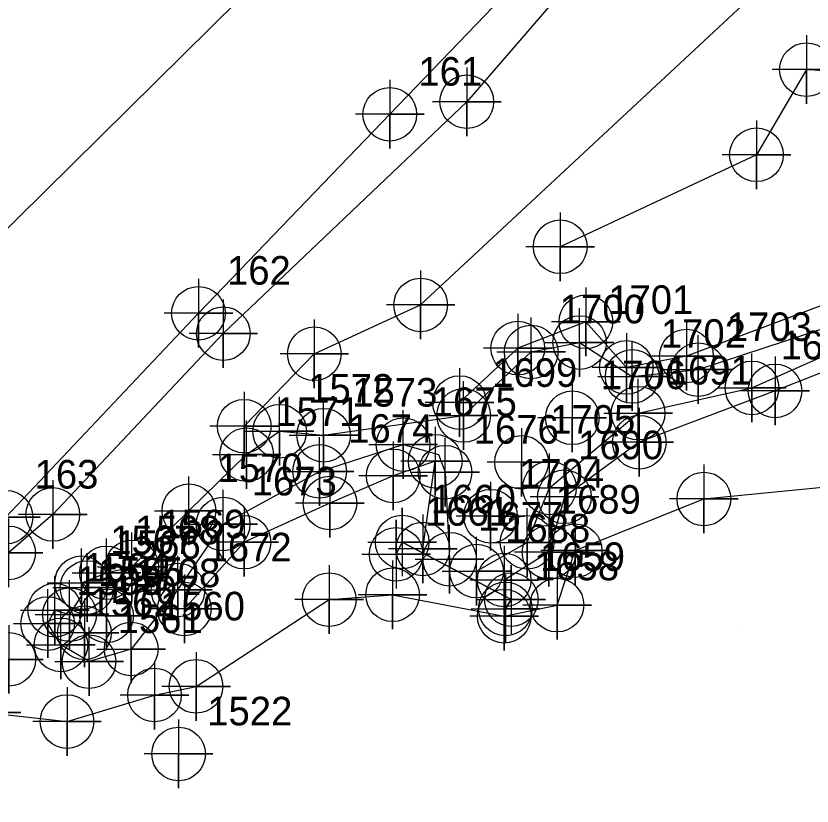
# Model space of a CAD drawing. Extents: x 1497074 to 1501343, y 481943 to 486114.
# Drawn here: x 1498485.9 to 1498555.5, y 484666.2 to 484735.3 of the extents above; entities that cross this region are included whole.
import ezdxf

# ---------------------------------------------------------------- set-up
doc = ezdxf.new("R2010")
doc.units = 0
for name, color, linetype in [('Exist DTM Breakline', 7, 'Continuous'), ('Exist DTM Breakline Cogo Point CELL', 7, 'Continuous'), ('Exist DTM Crownline', 7, 'Continuous'), ('Exist DTM Regular Point CELL', 7, 'Continuous'), ('Exist DTM Regular Point Cogo Number', 7, 'Continuous'), ('Exist DTM Regular Point Underwater CELL', 7, 'Continuous'), ('Exist DTM Regular Point Underwater Cogo Number', 7, 'Continuous'), ('Exist Hydro Stream or Body of Water', 7, 'Continuous'), ('Exist Hydro Stream or Body of Water Cogo Number', 7, 'Continuous'), ('Exist Hydro Stream or Body of Water Cogo Point CELL', 7, 'Continuous'), ('Exist Roads EOP', 7, 'Continuous'), ('Exist Roads EOP Cogo Number', 7, 'Continuous'), ('Exist Roads EOP Cogo Point CELL', 7, 'Continuous'), ('Exist Structure Minor Head and End Wall', 7, 'Continuous'), ('Exist Structure Minor Head and End Wall Cogo Number', 7, 'Continuous'), ('Exist Structure Minor Head and End Wall Cogo Point CELL', 7, 'Continuous'), ('PH Exist DTM Point', 7, 'Continuous')]:
    doc.layers.add(name, color=color, linetype=linetype)

msp = doc.modelspace()

# ---------------------------------------------------------------- linework, layer by layer
at = {"layer": 'Exist DTM Breakline'}
for points in [[(1498543.578, 484748.875), (1498525.356, 484727.773), (1498504.076, 484707.501), (1498489.168, 484691.702), (1498485.309, 484688.338), (1498482.582, 484685.278), (1498481.928, 484681.956), (1498482.729, 484679.638), (1498478.749, 484676.924), (1498480.53, 484675.332), (1498483.374, 484674.389), (1498490.413, 484673.601), (1498498.06, 484675.918), (1498501.691, 484676.673)], [(1498505.902, 484699.415), (1498512.029, 484705.743), (1498521.323, 484710.01), (1498551.972, 484738.6)], [(1498587.71, 484722.019), (1498578.881, 484728.622), (1498555.037, 484730.577), (1498550.672, 484723.134), (1498533.525, 484715.099)], [(1498561.972, 484712.059), (1498544.554, 484705.545), (1498539.303, 484704.549), (1498535.765, 484708.54), (1498529.808, 484706.236), (1498524.726, 484701.476)], [(1498568.235, 484707.531), (1498564.12, 484707.137), (1498552.295, 484702.499), (1498540.434, 484698.014), (1498533.886, 484693.244), (1498532.536, 484688.396), (1498528.621, 484685.97)], [(1498521.507, 484688.681), (1498522.593, 484696.353), (1498518.929, 484695.07), (1498513.394, 484692.699), (1498505.886, 484689.276), (1498500.67, 484683.439)], [(1498533.242, 484683.778), (1498534.825, 484688.535), (1498546.08, 484693.052), (1498568.33, 484695.244)], [(1498519.188, 484688.217), (1498519.707, 484689.291), (1498529.247, 484684.262), (1498528.727, 484683.445)], [(1498501.691, 484676.673), (1498513.329, 484684.253), (1498518.872, 484684.681), (1498528.629, 484682.804), (1498533.242, 484683.778)]]:
    msp.add_lwpolyline(points, dxfattribs=at)
at = {"layer": 'Exist DTM Breakline Cogo Point CELL'}
for points in [[(1498555.037, 484733.577), (1498555.037, 484727.577), (1498555.037, 484730.577), (1498558.037, 484730.577), (1498552.037, 484730.577)], [(1498525.356, 484730.773), (1498525.356, 484724.773), (1498525.356, 484727.773), (1498528.356, 484727.773), (1498522.356, 484727.773)], [(1498550.672, 484726.134), (1498550.672, 484720.134), (1498550.672, 484723.134), (1498553.672, 484723.134), (1498547.672, 484723.134)], [(1498533.525, 484718.099), (1498533.525, 484712.099), (1498533.525, 484715.099), (1498536.525, 484715.099), (1498530.525, 484715.099)], [(1498521.323, 484713.01), (1498521.323, 484707.01), (1498521.323, 484710.01), (1498524.323, 484710.01), (1498518.323, 484710.01)], [(1498535.765, 484711.54), (1498535.765, 484705.54), (1498535.765, 484708.54), (1498538.765, 484708.54), (1498532.765, 484708.54)], [(1498504.076, 484710.501), (1498504.076, 484704.501), (1498504.076, 484707.501), (1498507.076, 484707.501), (1498501.076, 484707.501)], [(1498512.029, 484708.743), (1498512.029, 484702.743), (1498512.029, 484705.743), (1498515.029, 484705.743), (1498509.029, 484705.743)], [(1498529.808, 484709.236), (1498529.808, 484703.236), (1498529.808, 484706.236), (1498532.808, 484706.236), (1498526.808, 484706.236)], [(1498544.554, 484708.545), (1498544.554, 484702.545), (1498544.554, 484705.545), (1498547.554, 484705.545), (1498541.554, 484705.545)], [(1498539.303, 484707.549), (1498539.303, 484701.549), (1498539.303, 484704.549), (1498542.303, 484704.549), (1498536.303, 484704.549)], [(1498552.295, 484705.499), (1498552.295, 484699.499), (1498552.295, 484702.499), (1498555.295, 484702.499), (1498549.295, 484702.499)], [(1498524.726, 484704.476), (1498524.726, 484698.476), (1498524.726, 484701.476), (1498527.726, 484701.476), (1498521.726, 484701.476)], [(1498505.902, 484702.415), (1498505.902, 484696.415), (1498505.902, 484699.415), (1498508.902, 484699.415), (1498502.902, 484699.415)], [(1498540.434, 484701.014), (1498540.434, 484695.014), (1498540.434, 484698.014), (1498543.434, 484698.014), (1498537.434, 484698.014)], [(1498522.593, 484699.353), (1498522.593, 484693.353), (1498522.593, 484696.353), (1498525.593, 484696.353), (1498519.593, 484696.353)], [(1498518.929, 484698.07), (1498518.929, 484692.07), (1498518.929, 484695.07), (1498521.929, 484695.07), (1498515.929, 484695.07)], [(1498533.886, 484696.244), (1498533.886, 484690.244), (1498533.886, 484693.244), (1498536.886, 484693.244), (1498530.886, 484693.244)], [(1498513.394, 484695.699), (1498513.394, 484689.699), (1498513.394, 484692.699), (1498516.394, 484692.699), (1498510.394, 484692.699)], [(1498546.08, 484696.052), (1498546.08, 484690.052), (1498546.08, 484693.052), (1498549.08, 484693.052), (1498543.08, 484693.052)], [(1498489.168, 484694.702), (1498489.168, 484688.702), (1498489.168, 484691.702), (1498492.168, 484691.702), (1498486.168, 484691.702)], [(1498505.886, 484692.276), (1498505.886, 484686.276), (1498505.886, 484689.276), (1498508.886, 484689.276), (1498502.886, 484689.276)], [(1498485.309, 484691.338), (1498485.309, 484685.338), (1498485.309, 484688.338), (1498488.309, 484688.338), (1498482.309, 484688.338)], [(1498521.507, 484691.681), (1498521.507, 484685.681), (1498521.507, 484688.681), (1498524.507, 484688.681), (1498518.507, 484688.681)], [(1498532.536, 484691.396), (1498532.536, 484685.396), (1498532.536, 484688.396), (1498535.536, 484688.396), (1498529.536, 484688.396)], [(1498534.825, 484691.535), (1498534.825, 484685.535), (1498534.825, 484688.535), (1498537.825, 484688.535), (1498531.825, 484688.535)], [(1498528.621, 484688.97), (1498528.621, 484682.97), (1498528.621, 484685.97), (1498531.621, 484685.97), (1498525.621, 484685.97)], [(1498513.329, 484687.253), (1498513.329, 484681.253), (1498513.329, 484684.253), (1498516.329, 484684.253), (1498510.329, 484684.253)], [(1498518.872, 484687.681), (1498518.872, 484681.681), (1498518.872, 484684.681), (1498521.872, 484684.681), (1498515.872, 484684.681)], [(1498500.67, 484686.439), (1498500.67, 484680.439), (1498500.67, 484683.439), (1498503.67, 484683.439), (1498497.67, 484683.439)], [(1498533.242, 484686.778), (1498533.242, 484680.778), (1498533.242, 484683.778), (1498536.242, 484683.778), (1498530.242, 484683.778)], [(1498528.629, 484685.804), (1498528.629, 484679.804), (1498528.629, 484682.804), (1498531.629, 484682.804), (1498525.629, 484682.804)], [(1498485.324, 484682.036), (1498485.324, 484676.036), (1498485.324, 484679.036), (1498488.324, 484679.036), (1498482.324, 484679.036)], [(1498501.691, 484679.673), (1498501.691, 484673.673), (1498501.691, 484676.673), (1498504.691, 484676.673), (1498498.691, 484676.673)], [(1498498.06, 484678.918), (1498498.06, 484672.918), (1498498.06, 484675.918), (1498501.06, 484675.918), (1498495.06, 484675.918)], [(1498483.374, 484677.389), (1498483.374, 484671.389), (1498483.374, 484674.389), (1498486.374, 484674.389), (1498480.374, 484674.389)], [(1498490.413, 484676.601), (1498490.413, 484670.601), (1498490.413, 484673.601), (1498493.413, 484673.601), (1498487.413, 484673.601)]]:
    msp.add_lwpolyline(points, dxfattribs=at)
for centre in [(1498555.037, 484730.577), (1498525.356, 484727.773), (1498550.672, 484723.134), (1498533.525, 484715.099), (1498521.323, 484710.01), (1498535.765, 484708.54), (1498504.076, 484707.501), (1498512.029, 484705.743), (1498529.808, 484706.236), (1498544.554, 484705.545), (1498539.303, 484704.549), (1498552.295, 484702.499), (1498524.726, 484701.476), (1498505.902, 484699.415), (1498540.434, 484698.014), (1498522.593, 484696.353), (1498518.929, 484695.07), (1498533.886, 484693.244), (1498513.394, 484692.699), (1498546.08, 484693.052), (1498489.168, 484691.702), (1498505.886, 484689.276), (1498485.309, 484688.338), (1498521.507, 484688.681), (1498532.536, 484688.396), (1498534.825, 484688.535), (1498528.621, 484685.97), (1498513.329, 484684.253), (1498518.872, 484684.681), (1498500.67, 484683.439), (1498533.242, 484683.778), (1498528.629, 484682.804), (1498485.324, 484679.036), (1498501.691, 484676.673), (1498498.06, 484675.918), (1498490.413, 484673.601)]:
    msp.add_circle(centre, 2.344, dxfattribs=at)
at = {"layer": 'Exist DTM Crownline'}
msp.add_lwpolyline([(1498174.514, 484418.762), (1498211.757, 484454.633), (1498248.883, 484490.298), (1498287.28, 484525.885), (1498324.11, 484560.628), (1498360.291, 484595.61), (1498397.16, 484630.832), (1498419.582, 484652.786), (1498435.06, 484667.859), (1498471.558, 484703.237), (1498507.821, 484739.068), (1498544.952, 484775.099), (1498579.438, 484811.194), (1498593.315, 484825.813), (1498614.797, 484848.72), (1498648.903, 484888.105), (1498682.161, 484928.338), (1498714.314, 484969.374), (1498734.432, 484994.616)], dxfattribs=at)
at = {"layer": 'Exist DTM Regular Point CELL'}
msp.add_lwpolyline([(1498500.168, 484673.764), (1498500.168, 484667.764), (1498500.168, 484670.764), (1498503.168, 484670.764), (1498497.168, 484670.764)], dxfattribs=at)
msp.add_circle((1498500.168, 484670.764), 2.344, dxfattribs=at)
at = {"layer": 'Exist DTM Regular Point Underwater CELL'}
for points in [[(1498534.576, 484703.149), (1498534.576, 484697.149), (1498534.576, 484700.149), (1498537.576, 484700.149), (1498531.576, 484700.149)], [(1498530.142, 484699.255), (1498530.142, 484693.255), (1498530.142, 484696.255), (1498533.142, 484696.255), (1498527.142, 484696.255)], [(1498527.428, 484694.545), (1498527.428, 484688.545), (1498527.428, 484691.545), (1498530.428, 484691.545), (1498524.428, 484691.545)], [(1498493.874, 484685.839), (1498493.874, 484679.839), (1498493.874, 484682.839), (1498496.874, 484682.839), (1498490.874, 484682.839)], [(1498491.934, 484684.356), (1498491.934, 484678.356), (1498491.934, 484681.356), (1498494.934, 484681.356), (1498488.934, 484681.356)]]:
    msp.add_lwpolyline(points, dxfattribs=at)
for centre in [(1498534.576, 484700.149), (1498530.142, 484696.255), (1498527.428, 484691.545), (1498493.874, 484682.839), (1498491.934, 484681.356)]:
    msp.add_circle(centre, 2.344, dxfattribs=at)
at = {"layer": 'Exist Hydro Stream or Body of Water'}
for points in [[(1498525.079, 484700.351), (1498530.984, 484705.901), (1498535.215, 484706.724), (1498539.814, 484703.763), (1498545.581, 484704.355), (1498562.802, 484710.019)], [(1498526.209, 484686.747), (1498530.628, 484689.26), (1498532.582, 484694.022), (1498540.326, 484700.553), (1498550.282, 484702.757), (1498562.565, 484708.225), (1498565.15, 484709.125)], [(1498500.114, 484685.097), (1498496.028, 484679.939), (1498492.337, 484678.836), (1498489.884, 484680.299), (1498488.723, 484682.163), (1498489.34, 484683.327), (1498490.64, 484682.943), (1498492.162, 484685.308), (1498491.69, 484685.733), (1498493.854, 484686.597), (1498496.074, 484687.115), (1498501.067, 484692.025), (1498506.115, 484696.925), (1498508.997, 484698.97), (1498512.842, 484698.626), (1498525.079, 484700.351)], [(1498500.114, 484685.097), (1498504.058, 484690.862), (1498512.492, 484695.463), (1498519.789, 484697.803), (1498522.871, 484696.953), (1498523.455, 484695.388), (1498523.853, 484687.786)]]:
    msp.add_lwpolyline(points, dxfattribs=at)
at = {"layer": 'Exist Hydro Stream or Body of Water Cogo Point CELL'}
for points in [[(1498532.215, 484706.724), (1498538.215, 484706.724), (1498535.215, 484706.724), (1498535.215, 484703.724), (1498535.215, 484709.724)], [(1498527.984, 484705.901), (1498533.984, 484705.901), (1498530.984, 484705.901), (1498530.984, 484702.901), (1498530.984, 484708.901)], [(1498542.581, 484704.355), (1498548.581, 484704.355), (1498545.581, 484704.355), (1498545.581, 484701.355), (1498545.581, 484707.355)], [(1498536.814, 484703.763), (1498542.814, 484703.763), (1498539.814, 484703.763), (1498539.814, 484700.763), (1498539.814, 484706.763)], [(1498547.282, 484702.757), (1498553.282, 484702.757), (1498550.282, 484702.757), (1498550.282, 484699.757), (1498550.282, 484705.757)], [(1498522.079, 484700.351), (1498528.079, 484700.351), (1498525.079, 484700.351), (1498525.079, 484697.351), (1498525.079, 484703.351)], [(1498537.326, 484700.553), (1498543.326, 484700.553), (1498540.326, 484700.553), (1498540.326, 484697.553), (1498540.326, 484703.553)], [(1498505.997, 484698.97), (1498511.997, 484698.97), (1498508.997, 484698.97), (1498508.997, 484695.97), (1498508.997, 484701.97)], [(1498509.842, 484698.626), (1498515.842, 484698.626), (1498512.842, 484698.626), (1498512.842, 484695.626), (1498512.842, 484701.626)], [(1498516.789, 484697.803), (1498522.789, 484697.803), (1498519.789, 484697.803), (1498519.789, 484694.803), (1498519.789, 484700.803)], [(1498503.115, 484696.925), (1498509.115, 484696.925), (1498506.115, 484696.925), (1498506.115, 484693.925), (1498506.115, 484699.925)], [(1498509.492, 484695.463), (1498515.492, 484695.463), (1498512.492, 484695.463), (1498512.492, 484692.463), (1498512.492, 484698.463)], [(1498520.455, 484695.388), (1498526.455, 484695.388), (1498523.455, 484695.388), (1498523.455, 484692.388), (1498523.455, 484698.388)], [(1498529.582, 484694.022), (1498535.582, 484694.022), (1498532.582, 484694.022), (1498532.582, 484691.022), (1498532.582, 484697.022)], [(1498498.067, 484692.025), (1498504.067, 484692.025), (1498501.067, 484692.025), (1498501.067, 484689.025), (1498501.067, 484695.025)], [(1498501.058, 484690.862), (1498507.058, 484690.862), (1498504.058, 484690.862), (1498504.058, 484687.862), (1498504.058, 484693.862)], [(1498527.628, 484689.26), (1498533.628, 484689.26), (1498530.628, 484689.26), (1498530.628, 484686.26), (1498530.628, 484692.26)], [(1498520.853, 484687.786), (1498526.853, 484687.786), (1498523.853, 484687.786), (1498523.853, 484684.786), (1498523.853, 484690.786)], [(1498493.074, 484687.115), (1498499.074, 484687.115), (1498496.074, 484687.115), (1498496.074, 484684.115), (1498496.074, 484690.115)], [(1498490.854, 484686.597), (1498496.854, 484686.597), (1498493.854, 484686.597), (1498493.854, 484683.597), (1498493.854, 484689.597)], [(1498523.209, 484686.747), (1498529.209, 484686.747), (1498526.209, 484686.747), (1498526.209, 484683.747), (1498526.209, 484689.747)], [(1498488.69, 484685.733), (1498494.69, 484685.733), (1498491.69, 484685.733), (1498491.69, 484682.733), (1498491.69, 484688.733)], [(1498489.162, 484685.308), (1498495.162, 484685.308), (1498492.162, 484685.308), (1498492.162, 484682.308), (1498492.162, 484688.308)], [(1498497.114, 484685.097), (1498503.114, 484685.097), (1498500.114, 484685.097), (1498500.114, 484682.097), (1498500.114, 484688.097)], [(1498486.34, 484683.327), (1498492.34, 484683.327), (1498489.34, 484683.327), (1498489.34, 484680.327), (1498489.34, 484686.327)], [(1498487.64, 484682.943), (1498493.64, 484682.943), (1498490.64, 484682.943), (1498490.64, 484679.943), (1498490.64, 484685.943)], [(1498485.723, 484682.163), (1498491.723, 484682.163), (1498488.723, 484682.163), (1498488.723, 484679.163), (1498488.723, 484685.163)], [(1498486.884, 484680.299), (1498492.884, 484680.299), (1498489.884, 484680.299), (1498489.884, 484677.299), (1498489.884, 484683.299)], [(1498493.028, 484679.939), (1498499.028, 484679.939), (1498496.028, 484679.939), (1498496.028, 484676.939), (1498496.028, 484682.939)], [(1498489.337, 484678.836), (1498495.337, 484678.836), (1498492.337, 484678.836), (1498492.337, 484675.836), (1498492.337, 484681.836)]]:
    msp.add_lwpolyline(points, dxfattribs=at)
for centre in [(1498535.215, 484706.724), (1498530.984, 484705.901), (1498545.581, 484704.355), (1498539.814, 484703.763), (1498550.282, 484702.757), (1498525.079, 484700.351), (1498540.326, 484700.553), (1498508.997, 484698.97), (1498512.842, 484698.626), (1498519.789, 484697.803), (1498506.115, 484696.925), (1498512.492, 484695.463), (1498523.455, 484695.388), (1498532.582, 484694.022), (1498501.067, 484692.025), (1498504.058, 484690.862), (1498530.628, 484689.26), (1498523.853, 484687.786), (1498496.074, 484687.115), (1498493.854, 484686.597), (1498526.209, 484686.747), (1498491.69, 484685.733), (1498492.162, 484685.308), (1498500.114, 484685.097), (1498489.34, 484683.327), (1498490.64, 484682.943), (1498488.723, 484682.163), (1498489.884, 484680.299), (1498496.028, 484679.939), (1498492.337, 484678.836)]:
    msp.add_circle(centre, 2.344, dxfattribs=at)
at = {"layer": 'Exist Roads EOP'}
msp.add_lwpolyline([(1498743.659, 484987.162), (1498738.498, 484978.991), (1498725.098, 484961.132), (1498703.009, 484933.772), (1498691.756, 484919.758), (1498658.665, 484879.665), (1498641.021, 484858.797), (1498630.746, 484847.819), (1498623.098, 484838.96), (1498603.65, 484817.74), (1498589.503, 484802.3), (1498575.555, 484786.504), (1498555.482, 484765.723), (1498538.212, 484747.039), (1498518.626, 484726.675), (1498501.899, 484709.282), (1498485.079, 484691.463), (1498474.433, 484677.642), (1498470.633, 484672.31)], dxfattribs=at)
at = {"layer": 'Exist Roads EOP Cogo Point CELL'}
for points in [[(1498518.626, 484729.675), (1498518.626, 484723.675), (1498518.626, 484726.675), (1498521.626, 484726.675), (1498515.626, 484726.675)], [(1498501.899, 484712.282), (1498501.899, 484706.282), (1498501.899, 484709.282), (1498504.899, 484709.282), (1498498.899, 484709.282)], [(1498485.079, 484694.463), (1498485.079, 484688.463), (1498485.079, 484691.463), (1498488.079, 484691.463), (1498482.079, 484691.463)]]:
    msp.add_lwpolyline(points, dxfattribs=at)
for centre in [(1498518.626, 484726.675), (1498501.899, 484709.282), (1498485.079, 484691.463)]:
    msp.add_circle(centre, 2.344, dxfattribs=at)
at = {"layer": 'Exist Structure Minor Head and End Wall'}
msp.add_lwpolyline([(1498528.727, 484683.445), (1498529.247, 484684.262), (1498519.707, 484689.291), (1498519.188, 484688.217)], dxfattribs=at)
at = {"layer": 'Exist Structure Minor Head and End Wall Cogo Point CELL'}
for points in [[(1498516.707, 484689.291), (1498522.707, 484689.291), (1498519.707, 484689.291), (1498519.707, 484692.291), (1498519.707, 484686.291)], [(1498516.188, 484688.217), (1498522.188, 484688.217), (1498519.188, 484688.217), (1498519.188, 484691.217), (1498519.188, 484685.217)], [(1498526.247, 484684.262), (1498532.247, 484684.262), (1498529.247, 484684.262), (1498529.247, 484687.262), (1498529.247, 484681.262)], [(1498525.727, 484683.445), (1498531.727, 484683.445), (1498528.727, 484683.445), (1498528.727, 484686.445), (1498528.727, 484680.445)]]:
    msp.add_lwpolyline(points, dxfattribs=at)
for centre in [(1498519.707, 484689.291), (1498519.188, 484688.217), (1498529.247, 484684.262), (1498528.727, 484683.445)]:
    msp.add_circle(centre, 2.344, dxfattribs=at)
at = {"layer": 'PH Exist DTM Point'}
msp.add_line((1498549.218, 484681.675), (1498549.218, 484681.675), dxfattribs=at)

# ---------------------------------------------------------------- texts
at = {"layer": 'Exist DTM Regular Point Cogo Number'}
msp.add_text('1522', height=2.5, dxfattribs=at).set_placement((1498502.668, 484673.264))
at = {"layer": 'Exist DTM Regular Point Underwater Cogo Number'}
for s, p in [('1706', (1498537.076, 484702.649)), ('1705', (1498532.642, 484698.755)), ('1704', (1498529.928, 484694.045)), ('1708', (1498496.374, 484685.339)), ('1707', (1498494.434, 484683.856))]:
    msp.add_text(s, height=2.5, dxfattribs=at).set_placement(p)
at = {"layer": 'Exist Hydro Stream or Body of Water Cogo Number'}
for s, p in [('1701', (1498537.715, 484709.224)), ('1700', (1498533.484, 484708.401)), ('1703', (1498548.081, 484706.855)), ('1702', (1498542.314, 484706.263)), ('1692', (1498552.782, 484705.257)), ('1699', (1498527.579, 484702.851)), ('1691', (1498542.826, 484703.053)), ('1572', (1498511.497, 484701.47)), ('1573', (1498515.342, 484701.126)), ('1675', (1498522.289, 484700.303)), ('1571', (1498508.615, 484699.425)), ('1674', (1498514.992, 484697.963)), ('1676', (1498525.955, 484697.888)), ('1690', (1498535.082, 484696.522)), ('1570', (1498503.567, 484694.525)), ('1673', (1498506.558, 484693.362)), ('1689', (1498533.128, 484691.76)), ('1677', (1498526.353, 484690.286)), ('1569', (1498498.574, 484689.615)), ('1568', (1498496.354, 484689.097)), ('1688', (1498528.709, 484689.247)), ('1567', (1498494.19, 484688.233)), ('1566', (1498494.662, 484687.808)), ('1672', (1498502.614, 484687.597)), ('1564', (1498491.84, 484685.827)), ('1565', (1498493.14, 484685.443)), ('1563', (1498491.223, 484684.663)), ('1562', (1498492.384, 484682.799)), ('1560', (1498498.528, 484682.439)), ('1561', (1498494.837, 484681.336))]:
    msp.add_text(s, height=2.5, dxfattribs=at).set_placement(p)
at = {"layer": 'Exist Roads EOP Cogo Number'}
for s, p in [('161', (1498521.126, 484729.175)), ('162', (1498504.399, 484711.782)), ('163', (1498487.579, 484693.963))]:
    msp.add_text(s, height=2.5, dxfattribs=at).set_placement(p)
at = {"layer": 'Exist Structure Minor Head and End Wall Cogo Number'}
for s, p in [('1660', (1498522.207, 484691.791)), ('1661', (1498521.688, 484690.717)), ('1659', (1498531.747, 484686.762)), ('1658', (1498531.227, 484685.945))]:
    msp.add_text(s, height=2.5, dxfattribs=at).set_placement(p)

doc.saveas('drawing.dxf')
